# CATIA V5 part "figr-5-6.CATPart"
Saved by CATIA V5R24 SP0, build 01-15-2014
Part number: Part1
Bounding box of the stored display mesh (mm): x 0 to 150, y -70 to 70, z -150 to 69.804
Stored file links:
  D:\KAVITA\CATIA V5-6R2014 Project_ Kavita\CATIA V5-6R2014_partfiles\Partfiles\c05_catia_v5-6r2014_prt\figr-5-6.CATPart
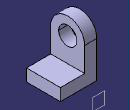
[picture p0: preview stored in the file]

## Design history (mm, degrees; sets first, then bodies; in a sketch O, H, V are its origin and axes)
Set1
  Plane1: type Offset, RefPlane face of Pad2, Offset 79, reversed
Body1 (main body)
  Sketch1 on yz-plane, origin (0, 0, 0), H (0, 1, 0), V (0, 0, 1)
    arc A1 centre (0, 0) radius 70 from (70, 0) to (-70, 0) ccw
    point P1 (70, 0)
    point P2 (-70, 0)
    line L1 (-70, 0) -> (-70, -150)
    line L2 (-70, -150) -> (70, -150)
    line L3 (70, -150) -> (70, 0)
    circle A2 centre (0, 0) radius 37.5
    radius A1 = 70
    radius A2 = 37.5
    distance O L2 = 150
    coincidence: P1 H, P2 H
    tangency: L1 A1, L3 A1
    horizontal: L2 H
  Pad1: profile Sketch1, direction (1, 0, 0), length 50
  Sketch2 on face of Pad1, origin (50, 0, 0), H (0, 1, 0), V (0, 0, 1)
    line L1 (-70, -150) -> (70, -150)
    line L2 (70, -150) -> (70, -100)
    line L3 (70, -100) -> (-70, -100)
    line L4 (-70, -100) -> (-70, -150)
    reference projected line E1 (-70, -150) -> (70, -150) from edge [face of Pad1 | face of Pad1]
    reference projected line E2 (-70, 0) -> (-70, -150) from edge [face of Pad1 | face of Pad1]
    reference projected line E3 (70, -150) -> (70, 0) from edge [face of Pad1 | face of Pad1]
    length L2 = 50
    horizontal: L1 H, L3 H
    vertical: L2 V, L4 V
    coincidence: L1 E1, E2 L4, L2 E3
  Pad2: profile Sketch2, direction (1, 0, 0), length 100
